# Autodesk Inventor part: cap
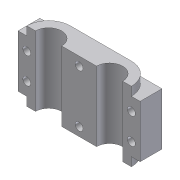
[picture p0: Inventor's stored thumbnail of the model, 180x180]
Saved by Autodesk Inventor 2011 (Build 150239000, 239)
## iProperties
Created: 2009-05
Part Number: cap
Document SubType Name: Modeling
Designer: Sham
Density: 1 g/cm^3
Author: Sham
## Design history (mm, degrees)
sketch "Sketch1"
  geometry: L1 (-35, 12.5)-(35, 12.5); L2 (35, 12.5)-(35, 0); L3 (35, 0)-(-35, 0); L4 (-35, 0)-(-35, 12.5); 2 further points
  constraints: 8 end point, 2 parallel, 1 coincident, 1 horizontal, 1 midpoint, 1 perpendicular, 1 other
  dimensions: "d0" = 12.5 distance of L3.end L1.start; "d1" = 70 distance of L2.end L3.end
extrude "Extrusion1" new body sketch "Sketch1" stored distance "d2" = 30; taper "d3" = 0 deg
sketch "Sketch2"
  geometry: L1 (30, 0)-(-30, 0); L2 (-17.5, 12.5)-(17.5, 12.5); L3 (-35, 12.5)-(35, 12.5) reference; L4 (35, 0)-(-35, 0) reference; A1 r 12.5 centre (-17.5, 0) between (-17.5, 12.5) and (-30, 0); A2 r 12.5 centre (17.5, 0) between (30, 0) and (17.5, 12.5); 1 further point
  constraints: 4 end point, 4 point on circle, 2 centre point, 2 collinear, 2 horizontal, 1 equal radius, 1 point on line, 1 tangent, 1 other
  dimensions: "d4" = 60 distance of L1.start L1.end; "d5" = 30 distance of point (0, 0) L1.start; "d6" = 12.5 radius of A2; "d7" = 35 distance of A1.centre A2.centre (derived)
extrude "Extrusion2" join sketch "Sketch2" stored distance "d8" = 40; taper "d9" = 0 deg
sketch "Sketch3"
  geometry: L1 (-25, 0)-(-10, 0); L2 (10, 0)-(25, 0); A1 r 12.5 centre (-17.5, 0) between (-17.5, 12.5) and (-30, 0) reference; A2 r 12.5 centre (17.5, 0) between (30, 0) and (17.5, 12.5) reference; A3 r 7.5 centre (-17.5, 0) between (-10, 0) and (-25, 0); A4 r 7.5 centre (17.5, 0) between (25, 0) and (10, 0)
  constraints: 4 end point, 4 point on circle, 2 centre point, 2 coincident, 2 horizontal, 1 equal radius
  dimensions: "d10" = 7.5 radius of A3
hole "Hole2" diameter "d25" = 4.5; stored, may be unused: countersink angle "d29" = 90 deg, drill point angle "d31" = 118 deg; dims "d23" = 7.5, "d24" = 5, "d26" = 6, "d27" = 4, "d28" = 2, "d30" = 15
pattern_linear "Rectangular Pattern2" dims "d34" = 15
extrude "Extrusion3" cut sketch "Sketch3" stored distance "d38" = 10; taper "d39" = 0 deg
hole "Hole3" diameter "d42" = 4.5; stored, may be unused: countersink angle "d46" = 90 deg, drill point angle "d48" = 118 deg; dims "d40" = 5, "d41" = 30, "d43" = 6, "d44" = 4, "d45" = 2, "d47" = 13
pattern_linear "Rectangular Pattern3" dims "d51" = 30
body "Solid1"
